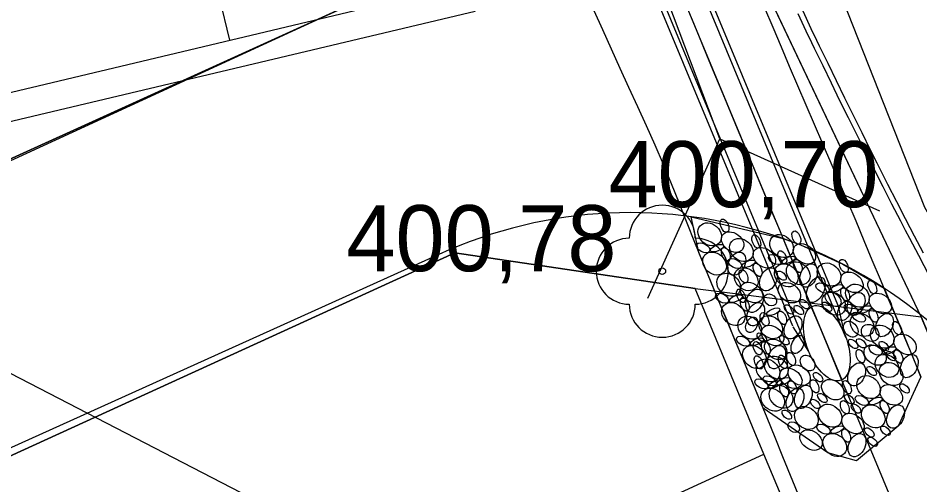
# Model space of a CAD drawing. Extents: x -574342 to -507939, y -1144044 to -1123894.
# Drawn here: x -508545.62 to -508531.96, y -1143262.87 to -1143255.8 of the extents above; entities that cross this region are included whole.
import ezdxf

# ---------------------------------------------------------------- set-up
doc = ezdxf.new("R2010")
doc.units = 0
for name, color, linetype in [('01_PARCELY_NAVRH_PC', 7, 'Continuous'), ('01_PARCELY_NAVRH_VHO', 7, 'Continuous'), ('01_PARCELY_NAVRH_ŽP', 7, 'Continuous'), ('04_ZPF_TECH_OPATŘEN_STAV', 7, 'Continuous'), ('1000', 7, 'Continuous'), ('21', 7, 'Continuous'), ('37', 7, 'Continuous'), ('42', 7, 'Continuous'), ('54', 7, 'Continuous'), ('cesty', 7, 'Continuous'), ('Level 255', 7, 'Continuous'), ('propustek', 7, 'Continuous'), ('SO 101_popis oblouku', 7, 'Continuous')]:
    doc.layers.add(name, color=color, linetype=linetype)

msp = doc.modelspace()

# ---------------------------------------------------------------- linework, layer by layer
msp.add_lwpolyline([(-508538.692, -1143255.691), (-508544.119, -1143232.805), (-508565.304, -1143237.829), (-508559.878, -1143260.714)], close=True)
at = {"layer": '01_PARCELY_NAVRH_PC'}
for points in [[(-508524.61, -1143277.77), (-508531.94, -1143260.32), (-508534.5, -1143254.93), (-508536.24, -1143250.83), (-508539.07, -1143243.44), (-508539.77, -1143241.25), (-508540.55, -1143238.43), (-508542.83, -1143228.38), (-508544.32, -1143217.47), (-508545.45, -1143205.07), (-508545.52, -1143198.58), (-508545.24, -1143191.32), (-508544.97, -1143188.3), (-508544.25, -1143181.83), (-508541.94, -1143173.53), (-508537.18, -1143176.51), (-508538.65, -1143182.46), (-508540.32, -1143193.28), (-508540.02, -1143209.35), (-508538.46, -1143221.35), (-508537.02, -1143231.11), (-508535.34, -1143238.37), (-508531.16, -1143250.06), (-508524.26, -1143263.08)], [(-508524.61, -1143277.77), (-508531.94, -1143260.32), (-508534.5, -1143254.93), (-508536.24, -1143250.83), (-508539.07, -1143243.44), (-508539.77, -1143241.25), (-508540.55, -1143238.43), (-508542.83, -1143228.38), (-508544.32, -1143217.47), (-508545.45, -1143205.07), (-508545.52, -1143198.58), (-508545.24, -1143191.32), (-508544.97, -1143188.3), (-508544.25, -1143181.83), (-508541.94, -1143173.53), (-508537.18, -1143176.51), (-508538.65, -1143182.46), (-508540.32, -1143193.28), (-508540.02, -1143209.35), (-508538.46, -1143221.35), (-508537.02, -1143231.11), (-508535.34, -1143238.37), (-508531.16, -1143250.06), (-508524.26, -1143263.08)], [(-508866.763, -1143529.283), (-508859.41, -1143516.97), (-508810.66, -1143431.99), (-508773.29, -1143386.75), (-508766.4, -1143380.31), (-508664.99, -1143316.89), (-508539, -1143259.35), (-508535.36, -1143259.89), (-508531.94, -1143260.32), (-508534.5, -1143254.93), (-508536.24, -1143250.83), (-508538.24, -1143253.15), (-508539.95, -1143255.3), (-508667.19, -1143313.15), (-508770.98, -1143377.64), (-508813.09, -1143427.79), (-508861.39, -1143510.97), (-508866.763, -1143520.059)]]:
    msp.add_lwpolyline(points, dxfattribs=at)
at = {"layer": '01_PARCELY_NAVRH_VHO'}
msp.add_lwpolyline([(-508497.13, -1143495.86), (-508497.34, -1143500.64), (-508499.94, -1143496.07), (-508501.52, -1143472.9), (-508509.71, -1143373.98), (-508513.61, -1143343.97), (-508516.21, -1143324.53), (-508518.91, -1143309.47), (-508522.63, -1143293.85), (-508527.23, -1143279.34), (-508534.32, -1143262.4), (-508535.36, -1143259.89), (-508531.94, -1143260.32), (-508524.61, -1143277.77), (-508522.34, -1143283.22), (-508517.78, -1143295.12), (-508517.67, -1143298.65), (-508514.79, -1143310.81), (-508512.2, -1143325.42), (-508505.85, -1143384.53), (-508502.4, -1143424.77), (-508500.25, -1143457.08), (-508499.28, -1143468.17)], close=True, dxfattribs=at)
at = {"layer": '01_PARCELY_NAVRH_ŽP'}
msp.add_lwpolyline([(-508555.03, -1143173.64), (-508548.66, -1143186.8), (-508549.63, -1143198.15), (-508549.79, -1143203.71), (-508547.53, -1143223.9), (-508542.99, -1143242.68), (-508538.24, -1143253.15), (-508539.95, -1143255.3), (-508547.25, -1143258.62), (-508651.11, -1143191.46), (-508662.59, -1143152.85), (-508637.59, -1143153.08), (-508621.09, -1143158.13), (-508610.87, -1143164.96), (-508585.59, -1143176.01), (-508569.25, -1143175.97)], close=True, dxfattribs=at)
msp.add_lwpolyline([(-508866.763, -1143539.171), (-508855.34, -1143520.06), (-508806.85, -1143435.07), (-508768.48, -1143388.71), (-508762.18, -1143383.5), (-508664.92, -1143322.31), (-508534.32, -1143262.4), (-508535.36, -1143259.89), (-508539, -1143259.35), (-508664.99, -1143316.89), (-508766.4, -1143380.31), (-508773.29, -1143386.75), (-508810.66, -1143431.99), (-508859.41, -1143516.97), (-508866.763, -1143529.283)], dxfattribs=at)
at = {"layer": '04_ZPF_TECH_OPATŘEN_STAV'}
for points in [[(-508534.989, -1143257.623), (-508537.197, -1143251.776)], [(-508536.08, -1143260.039), (-508534.989, -1143257.623), (-508532.572, -1143258.714)]]:
    msp.add_lwpolyline(points, dxfattribs=at)
at = {"layer": '1000'}
for points in [[(-508531.803, -1143267.874), (-508534.032, -1143262.444), (-508534.152, -1143262.148), (-508534.273, -1143261.853), (-508534.394, -1143261.558), (-508534.515, -1143261.263), (-508534.637, -1143260.968), (-508534.759, -1143260.672), (-508534.88, -1143260.378), (-508535.002, -1143260.083), (-508535.125, -1143259.788), (-508535.247, -1143259.493), (-508535.365, -1143259.197), (-508535.484, -1143258.9), (-508535.596, -1143258.621), (-508535.602, -1143258.604), (-508535.721, -1143258.308), (-508535.84, -1143258.012), (-508535.97, -1143257.72), (-508536.101, -1143257.429), (-508536.233, -1143257.138), (-508536.365, -1143256.847), (-508536.497, -1143256.557), (-508536.629, -1143256.266), (-508536.762, -1143255.976), (-508536.894, -1143255.685)], [(-508531.942, -1143261.23), (-508532.062, -1143260.935), (-508532.186, -1143260.641), (-508532.31, -1143260.346), (-508532.433, -1143260.052), (-508532.556, -1143259.757), (-508532.679, -1143259.463), (-508532.802, -1143259.168), (-508532.925, -1143258.874), (-508533.051, -1143258.581), (-508533.177, -1143258.288), (-508533.304, -1143257.995), (-508533.422, -1143257.718), (-508533.429, -1143257.701), (-508533.555, -1143257.408), (-508533.681, -1143257.115), (-508533.806, -1143256.821), (-508533.931, -1143256.528), (-508534.056, -1143256.234), (-508534.181, -1143255.94), (-508534.306, -1143255.646)], [(-508533.809, -1143255.724), (-508533.684, -1143255.988), (-508533.6, -1143256.165), (-508533.558, -1143256.252), (-508533.431, -1143256.516), (-508533.303, -1143256.779), (-508533.175, -1143257.042), (-508533.045, -1143257.304), (-508532.915, -1143257.566), (-508532.784, -1143257.827), (-508532.684, -1143258.025), (-508532.652, -1143258.088), (-508532.52, -1143258.349), (-508532.386, -1143258.609), (-508532.253, -1143258.869), (-508532.183, -1143259.007), (-508532.118, -1143259.129), (-508531.982, -1143259.388), (-508531.731, -1143259.865)], [(-508533.733, -1143255.688), (-508533.608, -1143255.952), (-508533.524, -1143256.129), (-508533.482, -1143256.216), (-508533.355, -1143256.479), (-508533.228, -1143256.742), (-508533.099, -1143257.005), (-508532.97, -1143257.267), (-508532.84, -1143257.529), (-508532.71, -1143257.79), (-508532.611, -1143257.988), (-508532.579, -1143258.051), (-508532.447, -1143258.312), (-508532.314, -1143258.572), (-508532.18, -1143258.832), (-508532.11, -1143258.969), (-508532.046, -1143259.092), (-508531.911, -1143259.351)]]:
    msp.add_lwpolyline(points, dxfattribs=at)
at = {"layer": '21'}
msp.add_lwpolyline([(-508530.606, -1143267.376), (-508532.858, -1143261.956), (-508532.98, -1143261.662), (-508533.103, -1143261.367), (-508533.225, -1143261.072), (-508533.348, -1143260.778), (-508533.47, -1143260.483), (-508533.593, -1143260.188), (-508533.715, -1143259.893), (-508533.837, -1143259.599), (-508533.96, -1143259.304), (-508534.082, -1143259.009), (-508534.205, -1143258.715), (-508534.327, -1143258.42), (-508534.443, -1143258.142), (-508534.45, -1143258.125), (-508534.572, -1143257.831), (-508534.695, -1143257.536), (-508534.817, -1143257.241), (-508534.939, -1143256.946), (-508535.062, -1143256.652), (-508535.184, -1143256.357), (-508535.307, -1143256.062), (-508535.429, -1143255.768)], dxfattribs=at)
at = {"layer": '37'}
msp.add_lwpolyline([(-508544.44, -1143182.59), (-508545.29, -1143193.14), (-508544.8, -1143205.6), (-508541.6, -1143228.19), (-508538.07, -1143243), (-508531.89, -1143258.66), (-508522.3, -1143275.29), (-508518.1, -1143283.75), (-508512.73, -1143299.25), (-508510.49, -1143313.12)], dxfattribs=at)
msp.add_lwpolyline([(-508544.44, -1143182.59), (-508545.29, -1143193.14), (-508544.8, -1143205.6), (-508541.6, -1143228.19), (-508538.07, -1143243), (-508531.89, -1143258.66), (-508522.3, -1143275.29), (-508518.1, -1143283.75), (-508512.73, -1143299.25), (-508510.49, -1143313.12)], dxfattribs=at)
at = {"layer": '42'}
msp.add_lwpolyline([(-508654.2, -1143191.6), (-508651.11, -1143191.46), (-508646.05, -1143192.58), (-508613.56, -1143216.76), (-508566.08, -1143248.87), (-508547.92, -1143260.05), (-508536.29, -1143266.06), (-508529.87, -1143271.02), (-508526.62, -1143279.23), (-508525.63, -1143286.24)], dxfattribs=at)
msp.add_lwpolyline([(-508654.2, -1143191.6), (-508651.11, -1143191.46), (-508646.05, -1143192.58), (-508613.56, -1143216.76), (-508566.08, -1143248.87), (-508547.92, -1143260.05), (-508536.29, -1143266.06), (-508529.87, -1143271.02), (-508526.62, -1143279.23), (-508525.63, -1143286.24)], dxfattribs=at)
at = {"layer": '54'}
msp.add_circle((-508535.86, -1143259.63), 0.05, dxfattribs=at)
for centre, start, end in [((-508535.86, -1143259.13), 0, 180), ((-508536.36, -1143259.63), 90, 270), ((-508535.36, -1143259.63), 270, 90), ((-508535.86, -1143260.13), 180, 0)]:
    msp.add_arc(centre, 0.5, start, end, dxfattribs=at)
at = {"layer": 'cesty'}
for p, q in [((-508541.033, -1143255.795), (-508665.409, -1143313.079)), ((-508539.243, -1143259.375), (-508664.164, -1143315.809))]:
    msp.add_line(p, q, dxfattribs=at)
for centre, start, end in [((-508543.938, -1143249.426), 294.5203, 21.1483), ((-508536.338, -1143265.744), 28.6901, 114.5203)]:
    msp.add_arc(centre, 7, start, end, dxfattribs=at)
at = {"layer": 'propustek'}
for p, q in [((-508537.335, -1143250.399), (-508533.084, -1143260.63)), ((-508537.882, -1143250.646), (-508533.651, -1143260.831)), ((-508537.566, -1143250.623), (-508533.141, -1143261.276)), ((-508537.103, -1143250.761), (-508533.181, -1143260.194)), ((-508537.793, -1143251.06), (-508533.888, -1143260.46)), ((-508533.088, -1143260.614), (-508533.184, -1143260.183)), ((-508533.642, -1143260.845), (-508533.88, -1143260.473))]:
    msp.add_line(p, q, dxfattribs=at)
msp.add_lwpolyline([(-508534.334, -1143261.705), (-508534.637, -1143260.968), (-508534.941, -1143260.23), (-508535.306, -1143259.345), (-508535.421, -1143258.804), (-508534.03, -1143259.135), (-508533.766, -1143259.233), (-508533.127, -1143259.523), (-508532.501, -1143259.889), (-508532.186, -1143260.641), (-508531.942, -1143261.23), (-508532.29, -1143261.978), (-508532.917, -1143262.503), (-508533.351, -1143262.379)], close=True, dxfattribs=at)
for centre, major_axis, ratio in [((-508535.141, -1143259.071), (-0.146, 0.13), 0.799162), ((-508534.917, -1143258.941), (-0.0411, 0.0988), 0.545699), ((-508533.829, -1143259.12), (-0.0411, 0.0988), 0.545699), ((-508534.795, -1143259.189), (-0.149, 0.112), 0.724539), ((-508534.661, -1143259.308), (-0.146, 0.13), 0.799162), ((-508534.437, -1143259.179), (-0.0411, 0.0988), 0.545699), ((-508534.053, -1143259.249), (-0.146, 0.13), 0.799162), ((-508535.241, -1143259.275), (-0.0956, 0.0524), 0.579616), ((-508535.032, -1143259.281), (0.0988, 0.0411), 0.409091), ((-508534.897, -1143259.372), (-0.0411, 0.0988), 0.545699), ((-508534.315, -1143259.426), (-0.149, 0.112), 0.724539), ((-508533.707, -1143259.367), (-0.149, 0.112), 0.724539), ((-508535.069, -1143259.514), (-0.146, 0.13), 0.799162), ((-508534.732, -1143259.516), (0.077, 0.169), 0.657512), ((-508534.153, -1143259.453), (-0.0956, 0.0524), 0.579616), ((-508534.043, -1143259.42), (-0.0411, 0.0988), 0.545699), ((-508533.945, -1143259.459), (0.0988, 0.0411), 0.409091), ((-508534.761, -1143259.512), (-0.0956, 0.0524), 0.579616), ((-508534.589, -1143259.751), (-0.146, 0.13), 0.799162), ((-508534.552, -1143259.518), (0.0988, 0.0411), 0.409091), ((-508534.416, -1143259.609), (-0.0411, 0.0988), 0.545699), ((-508534.252, -1143259.754), (0.077, 0.169), 0.657512), ((-508533.982, -1143259.692), (-0.146, 0.13), 0.799162), ((-508533.802, -1143259.663), (-0.146, 0.13), 0.799162), ((-508533.809, -1143259.55), (-0.0411, 0.0988), 0.545699), ((-508533.644, -1143259.694), (0.077, 0.169), 0.657512), ((-508533.334, -1143259.68), (-0.146, 0.13), 0.799162), ((-508533.11, -1143259.551), (-0.0411, 0.0988), 0.545699), ((-508534.854, -1143259.836), (-0.146, 0.13), 0.799162), ((-508534.63, -1143259.706), (-0.0411, 0.0988), 0.545699), ((-508534.054, -1143259.698), (-0.0641, 0.0611), 0.557809), ((-508533.535, -1143259.91), (-0.089, -0.187), 0.586676), ((-508532.988, -1143259.798), (-0.149, 0.112), 0.724539), ((-508534.508, -1143259.953), (-0.149, 0.112), 0.724539), ((-508533.935, -1143259.956), (-0.149, 0.112), 0.724539), ((-508533.434, -1143259.884), (-0.0956, 0.0524), 0.579616), ((-508533.225, -1143259.89), (0.0988, 0.0411), 0.409091), ((-508532.904, -1143260), (-0.146, 0.13), 0.799162), ((-508532.68, -1143259.871), (-0.0411, 0.0988), 0.545699), ((-508534.955, -1143260.039), (-0.0956, 0.0524), 0.579616), ((-508534.668, -1143260.003), (-0.0411, 0.0988), 0.545699), ((-508534.461, -1143260.078), (0.077, 0.169), 0.657512), ((-508534.224, -1143260.065), (0.0766, -0.0679), 0.799162), ((-508533.262, -1143260.123), (-0.146, 0.13), 0.799162), ((-508533.273, -1143260.055), (-0.106, 0.086), 0.657512), ((-508533.09, -1143259.981), (-0.0411, 0.0988), 0.545699), ((-508532.925, -1143260.126), (0.077, 0.169), 0.657512), ((-508532.558, -1143260.118), (-0.149, 0.112), 0.724539), ((-508534.783, -1143260.279), (-0.146, 0.13), 0.799162), ((-508534.746, -1143260.045), (0.0988, 0.0411), 0.409091), ((-508534.61, -1143260.136), (-0.0411, 0.0988), 0.545699), ((-508534.445, -1143260.281), (0.077, 0.169), 0.657512), ((-508533.709, -1143260.129), (-0.0641, 0.0611), 0.557809), ((-508533.368, -1143260.721), (-0.214, 0.561), 0.499987), ((-508533.367, -1143260.169), (-0.0641, 0.0611), 0.557809), ((-508533.098, -1143260.23), (-0.068, -0.143), 0.586676), ((-508534.311, -1143260.357), (-0.0411, 0.0988), 0.545699), ((-508534.18, -1143260.245), (0.0988, 0.0411), 0.409091), ((-508534.045, -1143260.336), (-0.0411, 0.0988), 0.545699), ((-508533.941, -1143260.209), (-0.0641, 0.0611), 0.557809), ((-508533.792, -1143260.218), (-0.0641, 0.0611), 0.557809), ((-508533.005, -1143260.204), (-0.0956, 0.0524), 0.579616), ((-508532.884, -1143260.325), (-0.0956, 0.0524), 0.579616), ((-508532.796, -1143260.21), (0.0988, 0.0411), 0.409091), ((-508532.66, -1143260.301), (-0.0411, 0.0988), 0.545699), ((-508534.536, -1143260.486), (-0.146, 0.13), 0.799162), ((-508534.507, -1143260.442), (0.052, 0.113), 0.657512), ((-508534.217, -1143260.478), (-0.146, 0.13), 0.799162), ((-508533.88, -1143260.48), (0.077, 0.169), 0.657512), ((-508533.005, -1143260.509), (-0.078, 0.106), 0.73939), ((-508532.833, -1143260.443), (-0.146, 0.13), 0.799162), ((-508532.495, -1143260.446), (0.077, 0.169), 0.657512), ((-508532.305, -1143260.492), (-0.0411, 0.0988), 0.545699), ((-508534.19, -1143260.604), (-0.149, 0.112), 0.724539), ((-508532.712, -1143260.564), (-0.108, 0.096), 0.799162), ((-508532.529, -1143260.621), (-0.146, 0.13), 0.799162), ((-508534.636, -1143260.69), (-0.0956, 0.0524), 0.579616), ((-508534.427, -1143260.696), (0.0988, 0.0411), 0.409091), ((-508534.353, -1143260.636), (-0.0641, 0.0611), 0.557809), ((-508534.142, -1143260.814), (-0.149, 0.112), 0.724539), ((-508534.011, -1143260.676), (-0.0641, 0.0611), 0.557809), ((-508533.811, -1143260.74), (-0.062, -0.132), 0.586676), ((-508532.969, -1143260.732), (-0.0641, 0.0611), 0.557809), ((-508532.847, -1143260.723), (-0.0641, 0.0611), 0.557809), ((-508532.183, -1143260.739), (-0.149, 0.112), 0.724539), ((-508534.464, -1143260.929), (-0.146, 0.13), 0.799162), ((-508534.417, -1143260.797), (-0.0411, 0.0988), 0.545699), ((-508534.291, -1143260.787), (-0.0411, 0.0988), 0.545699), ((-508534.127, -1143260.931), (0.077, 0.169), 0.657512), ((-508532.636, -1143260.9), (-0.149, 0.112), 0.724539), ((-508532.629, -1143260.825), (-0.0956, 0.0524), 0.579616), ((-508532.505, -1143260.763), (-0.0641, 0.0611), 0.557809), ((-508532.421, -1143260.831), (0.0988, 0.0411), 0.409091), ((-508534.4, -1143261.011), (-0.0411, 0.0988), 0.545699), ((-508534.133, -1143261.089), (-0.146, 0.13), 0.799162), ((-508534.035, -1143261.003), (-0.0411, 0.0988), 0.545699), ((-508533.909, -1143260.959), (-0.0411, 0.0988), 0.545699), ((-508533.659, -1143261.021), (-0.078, 0.106), 0.73939), ((-508532.859, -1143260.917), (-0.0411, 0.0988), 0.545699), ((-508532.458, -1143261.064), (-0.146, 0.13), 0.799162), ((-508532.395, -1143260.915), (-0.0641, 0.0611), 0.557809), ((-508532.285, -1143260.922), (-0.0411, 0.0988), 0.545699), ((-508532.12, -1143261.067), (0.077, 0.169), 0.657512), ((-508534.259, -1143261.133), (-0.146, 0.13), 0.799162), ((-508533.787, -1143261.206), (-0.149, 0.112), 0.724539), ((-508532.917, -1143261.193), (0.077, 0.169), 0.657512), ((-508532.688, -1143261.142), (-0.0641, 0.0611), 0.557809), ((-508532.394, -1143261.188), (-0.146, 0.13), 0.799162), ((-508533.913, -1143261.25), (-0.149, 0.112), 0.724539), ((-508533.501, -1143261.235), (-0.0641, 0.0611), 0.557809), ((-508532.736, -1143261.386), (-0.146, 0.13), 0.799162), ((-508534.359, -1143261.336), (-0.0956, 0.0524), 0.579616), ((-508534.233, -1143261.292), (-0.0956, 0.0524), 0.579616), ((-508534.062, -1143261.532), (-0.146, 0.13), 0.799162), ((-508534.151, -1143261.342), (0.0988, 0.0411), 0.409091), ((-508534.025, -1143261.299), (0.0988, 0.0411), 0.409091), ((-508534.015, -1143261.433), (-0.0411, 0.0988), 0.545699), ((-508533.889, -1143261.39), (-0.0411, 0.0988), 0.545699), ((-508533.724, -1143261.534), (0.077, 0.169), 0.657512), ((-508533.555, -1143261.373), (-0.0411, 0.0988), 0.545699), ((-508533.278, -1143261.425), (-0.149, 0.112), 0.724539), ((-508533.063, -1143261.387), (-0.0411, 0.0988), 0.545699), ((-508532.391, -1143261.504), (-0.149, 0.112), 0.724539), ((-508532.191, -1143261.406), (-0.0641, 0.0611), 0.557809), ((-508534.188, -1143261.576), (-0.146, 0.13), 0.799162), ((-508533.85, -1143261.578), (0.077, 0.169), 0.657512), ((-508533.435, -1143261.551), (-0.0641, 0.0611), 0.557809), ((-508533.542, -1143261.641), (-0.0641, 0.0611), 0.557809), ((-508533.095, -1143261.69), (-0.0411, 0.0988), 0.545699), ((-508533.026, -1143261.57), (-0.0641, 0.0611), 0.557809), ((-508532.837, -1143261.59), (-0.0956, 0.0524), 0.579616), ((-508532.628, -1143261.596), (0.0988, 0.0411), 0.409091), ((-508532.492, -1143261.687), (-0.0411, 0.0988), 0.545699), ((-508533.973, -1143261.803), (-0.0641, 0.0611), 0.557809), ((-508533.678, -1143261.852), (-0.146, 0.13), 0.799162), ((-508533.319, -1143261.819), (-0.146, 0.13), 0.799162), ((-508532.926, -1143261.711), (-0.0641, 0.0611), 0.557809), ((-508532.665, -1143261.829), (-0.146, 0.13), 0.799162), ((-508532.327, -1143261.832), (0.077, 0.169), 0.657512), ((-508532.973, -1143261.937), (-0.149, 0.112), 0.724539), ((-508533.871, -1143261.993), (-0.0777, 0.0583), 0.724539), ((-508533.607, -1143262.188), (-0.149, 0.112), 0.724539), ((-508533.419, -1143262.023), (-0.0956, 0.0524), 0.579616), ((-508533.21, -1143262.029), (0.0988, 0.0411), 0.409091), ((-508533.075, -1143262.12), (-0.0411, 0.0988), 0.545699), ((-508532.723, -1143262.073), (-0.0641, 0.0611), 0.557809), ((-508532.48, -1143262.046), (-0.0641, 0.0611), 0.557809), ((-508533.247, -1143262.262), (-0.146, 0.13), 0.799162), ((-508532.91, -1143262.265), (0.077, 0.169), 0.657512), ((-508532.674, -1143262.214), (-0.0641, 0.0611), 0.557809)]:
    msp.add_ellipse(centre, major_axis=major_axis, ratio=ratio, dxfattribs=at)
at = {"layer": 'SO 101_popis oblouku'}
for p, q in [((-508542.409, -1143256.132), (-508547.685, -1143234.088)), ((-508539.103, -1143255.341), (-508555.636, -1143259.298))]:
    msp.add_line(p, q, dxfattribs=at)

# ---------------------------------------------------------------- texts
at = {"layer": 'Level 255'}
for s, p in [('400,70', (-508536.675, -1143258.66)), ('400,78', (-508540.645, -1143259.63))]:
    msp.add_text(s, height=1, dxfattribs=at).set_placement(p)

doc.saveas('drawing.dxf')
